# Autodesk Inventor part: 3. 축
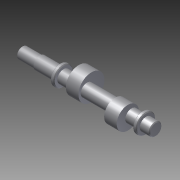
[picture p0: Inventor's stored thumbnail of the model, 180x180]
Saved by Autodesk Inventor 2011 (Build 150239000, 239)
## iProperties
Created: 2014-12
Part Number: 3. 축
Document SubType Name: Modeling
Designer: user
Density: 1 g/cm^3
Author: user
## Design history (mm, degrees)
sketch "스케치1"
  geometry: L1 (-90, 0)-(90, 0); L2 (-90, 0)-(-90, 7.5); L3 (-90, 7.5)-(-66, 7.5); L4 (-66, 7.5)-(-66, 8.5); L5 (-66, 8.5)-(-39, 8.5); L6 (-39, 8.5)-(-39, 13); L7 (-39, 13)-(-34, 13); L8 (-34, 13)-(-34, 8.5); L9 (-34, 8.5)-(72, 8.5); L10 (72, 8.5)-(72, 13); L11 (72, 13)-(77, 13); L12 (77, 13)-(77, 8.5); L13 (77, 8.5)-(90, 8.5); L14 (90, 8.5)-(90, 0); 2 further points
  constraints: 28 end point, 11 parallel, 2 perpendicular, 1 coincident, 1 horizontal, 1 midpoint
  dimensions: "d0" = 180 distance of L1.start L1.end; "d1" = 24 distance of L2.end L3.end; "d2" = 27 distance of L4.end L5.end; "d3" = 5 distance of L6.end L7.end; "d4" = 5 distance of L10.end L11.end; "d5" = 13 distance of L12.end L13.end; "d6" = 15 diameter of L3 L1; "d7" = 17 diameter of L5 L1; "d8" = 26 diameter of L7 L1; "d9" = 17 diameter of L13 L1; "d10" = 26 diameter of L11 L1; "d11" = 17 diameter of L9 L1
revolve "회전1" sketch "스케치1" stored, may be unused: angle "d12" = 90 deg
sketch "스케치2"
  geometry: L1 (-90, -7.5)-(-90, 7.5) reference; L2 (-90, 7.5)-(-66, 7.5) reference; L3 (-66, 7.5)-(-66, 8.5) reference; L4 (-66, 8.5)-(-39, 8.5) reference; L5 (-39, 8.5)-(-39, 13) reference; L6 (-39, 13)-(-34, 13) reference; L7 (-34, 13)-(-34, 8.5) reference; L8 (-34, 8.5)-(72, 8.5) reference; L9 (72, 8.5)-(72, 13) reference; L10 (72, 13)-(77, 13) reference; L11 (77, 13)-(77, 8.5) reference; L12 (77, 8.5)-(90, 8.5) reference; L13 (90, 8.5)-(90, -8.5) reference; L14 (90, -8.5)-(77, -8.5) reference; L15 (77, -8.5)-(77, -13) reference; L16 (77, -13)-(72, -13) reference; L17 (72, -13)-(72, -8.5) reference; L18 (72, -8.5)-(-34, -8.5) reference; L19 (-34, -8.5)-(-34, -13) reference; L20 (-34, -13)-(-39, -13) reference; L21 (-39, -13)-(-39, -8.5) reference; L22 (-39, -8.5)-(-66, -8.5) reference; L23 (-66, -8.5)-(-66, -7.5) reference; L24 (-66, -7.5)-(-90, -7.5) reference; L25 (-70, 7.5)-(-90, 7.5); L26 (-90, 7.5)-(-90, 4.5); L27 (-90, 4.5)-(-70, 4.5); L28 (-70, 4.5)-(-70, 7.5); 1 further point
  constraints: 8 end point, 2 parallel, 2 point on line, 1 horizontal, 1 perpendicular
  dimensions: "d13" = 20 distance of L26.end L27.end; "d14" = 3 distance of L27.end L25.start
extrude "돌출1" cut sketch "스케치2" stored distance "d15" = 5; taper "d16" = 0 deg
fillet "모깎기1" dims "d17" = 2.5
chamfer "모따기1" distance "d18" = 1; stored, may be unused: second distance "d19" = 2, angle "d20" = 45 deg
chamfer "모따기2" distance "d21" = 1; stored, may be unused: second distance "d22" = 2, angle "d23" = 45 deg
node "작업 평면1"
sketch "스케치3"
  geometry: C1 r 8.5 at (0, 0) reference; C2 r 17.5 at (0, 6); C3 r 13 at (0, 0) reference; C4 r 12 at (0, 0) reference; 1 further point
  constraints: 1 centre point, 1 vertical alignment
  dimensions: "d25" = 35 diameter of C2; "d26" = 6 distance of point (0, 0) C2.centre
extrude "돌출2" join sketch "스케치3" distance "d27" = 17; taper "d28" = 0 deg
node "작업 평면2"
sketch "스케치4"
  geometry: C1 r 8.5 at (0, 0) reference; C2 r 12 at (0, 0) reference; C3 r 13 at (0, 0) reference; C4 r 15 at (0, -5); 1 further point
  constraints: 1 centre point, 1 vertical alignment
  dimensions: "d30" = 30 diameter of C4; "d31" = 5 distance of point (0, 0) C4.centre
extrude "돌출3" join sketch "스케치4" distance "d32" = 17; taper "d33" = 0 deg
node "솔리드1"
node "절단 모서리 투영1"
node "절단 모서리 투영2"
node "절단 모서리 투영3"
other parameters: "d24" = 14.5, "d29" = 14.5
